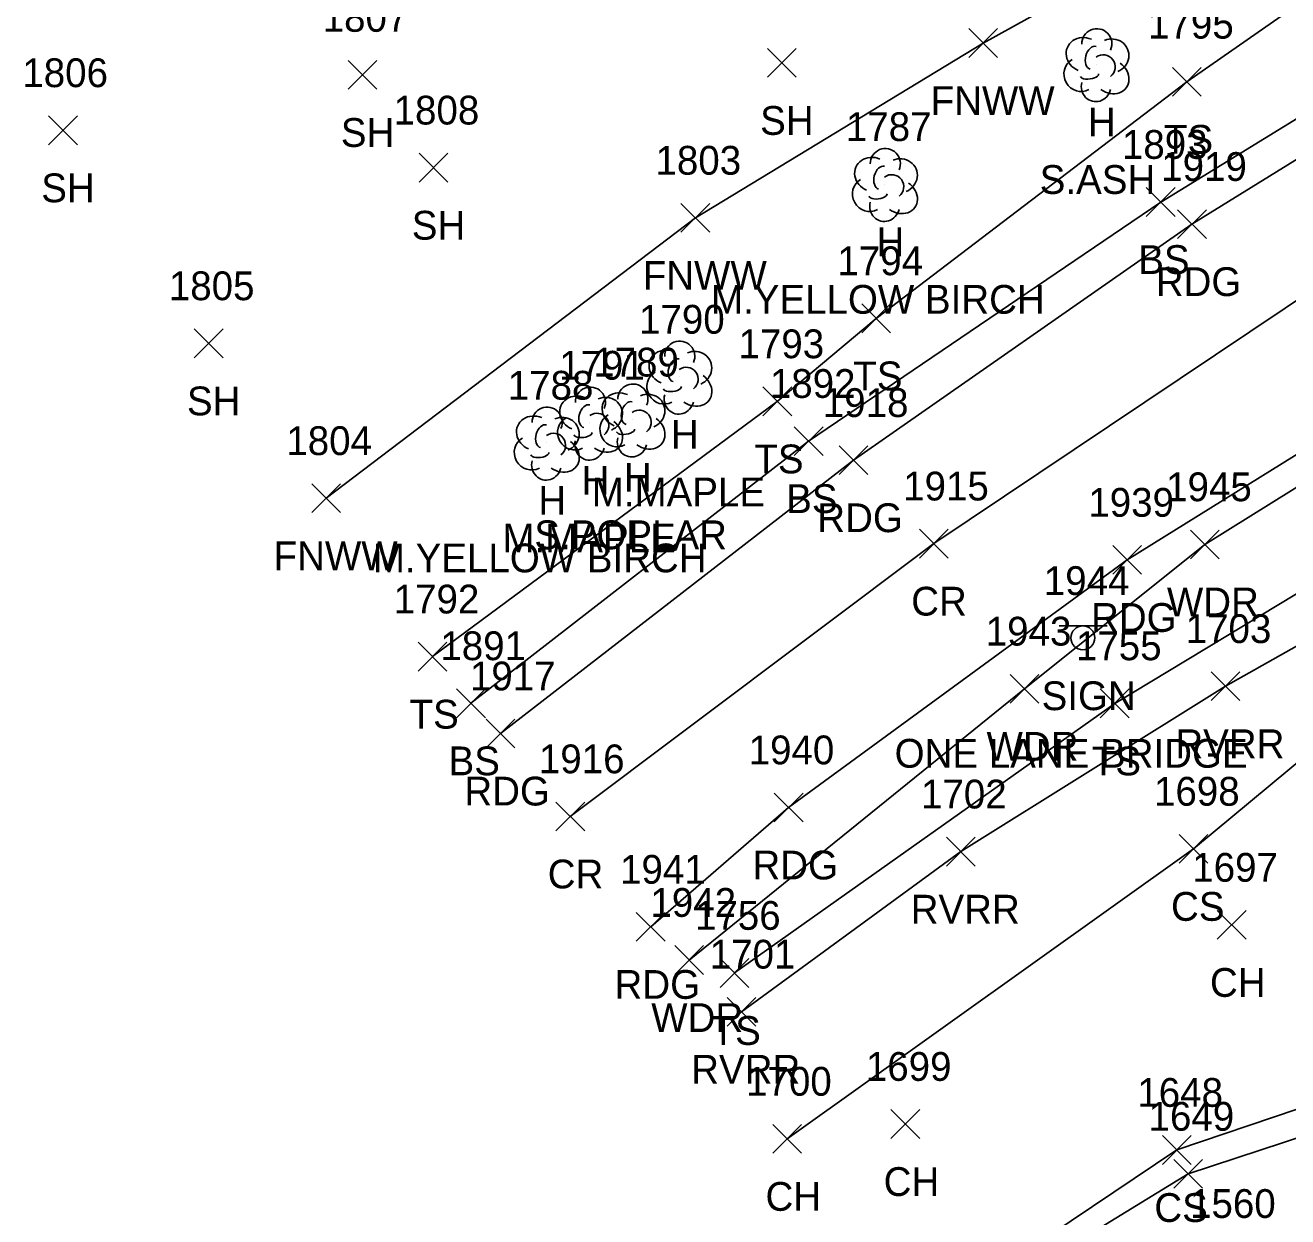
# Model space of a CAD drawing. Extents: x 1621633 to 1624015, y 417863 to 420979.
# Drawn here: x 1621633.1 to 1621720.8, y 417953.8 to 418036.6 of the extents above; entities that cross this region are included whole.
import ezdxf

# ---------------------------------------------------------------- set-up
doc = ezdxf.new("R2010")
doc.units = 0
for name, color, linetype in [('L_A', 7, 'Continuous'), ('L_C', 7, 'Continuous'), ('L_I', 7, 'Continuous'), ('L_TIC', 7, 'Continuous'), ('LAWA', 7, 'Continuous'), ('LAWE', 7, 'Continuous'), ('LELB', 7, 'Continuous'), ('LFNC', 7, 'Continuous'), ('LTD', 7, 'Continuous'), ('P_A', 7, 'Continuous'), ('P_I', 7, 'Continuous'), ('P_TIC', 7, 'Continuous'), ('PEU', 7, 'Continuous'), ('PRC', 7, 'Continuous'), ('S_A', 7, 'Continuous'), ('S_C', 7, 'Continuous'), ('S_I', 7, 'Continuous'), ('SSGN', 7, 'Continuous')]:
    doc.layers.add(name, color=color, linetype=linetype)

msp = doc.modelspace()

# ---------------------------------------------------------------- linework, layer by layer
at = {"layer": 'L_TIC'}
for points in [[(1621698.616, 418034.317), (1621700.616, 418036.317)], [(1621700.616, 418034.317), (1621698.616, 418036.317)], [(1621684.631, 418032.936), (1621686.631, 418034.936)], [(1621686.631, 418032.936), (1621684.631, 418034.936)], [(1621655.507, 418032.1), (1621657.507, 418034.1)], [(1621657.507, 418032.1), (1621655.507, 418034.1)], [(1621712.758, 418031.625), (1621714.758, 418033.625)], [(1621714.758, 418031.625), (1621712.758, 418033.625)], [(1621634.699, 418028.253), (1621636.699, 418030.253)], [(1621636.699, 418028.253), (1621634.699, 418030.253)], [(1621660.434, 418025.655), (1621662.434, 418027.655)], [(1621662.434, 418025.655), (1621660.434, 418027.655)], [(1621710.941, 418023.269), (1621712.941, 418025.269)], [(1621712.941, 418023.269), (1621710.941, 418025.269)], [(1621678.621, 418022.169), (1621680.621, 418024.169)], [(1621680.621, 418022.169), (1621678.621, 418024.169)], [(1621691.18, 418015.185), (1621693.18, 418017.185)], [(1621693.18, 418015.185), (1621691.18, 418017.185)], [(1621644.819, 418013.447), (1621646.819, 418015.447)], [(1621646.819, 418013.447), (1621644.819, 418015.447)], [(1621684.31, 418009.415), (1621686.31, 418011.415)], [(1621686.31, 418009.415), (1621684.31, 418011.415)], [(1621686.487, 418006.656), (1621688.487, 418008.656)], [(1621688.487, 418006.656), (1621686.487, 418008.656)], [(1621652.982, 418002.684), (1621654.982, 418004.684)], [(1621654.982, 418002.684), (1621652.982, 418004.684)], [(1621714.012, 417999.477), (1621716.012, 418001.477)], [(1621716.012, 417999.477), (1621714.012, 418001.477)], [(1621660.358, 417991.677), (1621662.358, 417993.677)], [(1621662.358, 417991.677), (1621660.358, 417993.677)], [(1621701.483, 417989.446), (1621703.483, 417991.446)], [(1621703.483, 417989.446), (1621701.483, 417991.446)], [(1621715.448, 417989.621), (1621717.448, 417991.621)], [(1621717.448, 417989.621), (1621715.448, 417991.621)], [(1621663.034, 417988.432), (1621665.034, 417990.432)], [(1621665.034, 417988.432), (1621663.034, 417990.432)], [(1621707.748, 417988.428), (1621709.748, 417990.428)], [(1621709.748, 417988.428), (1621707.748, 417990.428)], [(1621697.064, 417978.126), (1621699.064, 417980.126)], [(1621699.064, 417978.126), (1621697.064, 417980.126)], [(1621713.218, 417978.319), (1621715.218, 417980.319)], [(1621715.218, 417978.319), (1621713.218, 417980.319)], [(1621715.875, 417973.035), (1621717.875, 417975.035)], [(1621717.875, 417973.035), (1621715.875, 417975.035)], [(1621678.191, 417970.595), (1621680.191, 417972.595)], [(1621680.191, 417970.595), (1621678.191, 417972.595)], [(1621681.341, 417969.694), (1621683.341, 417971.694)], [(1621683.341, 417969.694), (1621681.341, 417971.694)], [(1621681.822, 417966.998), (1621683.822, 417968.998)], [(1621683.822, 417966.998), (1621681.822, 417968.998)], [(1621693.209, 417959.197), (1621695.209, 417961.197)], [(1621695.209, 417959.197), (1621693.209, 417961.197)], [(1621685.004, 417958.166), (1621687.004, 417960.166)], [(1621687.004, 417958.166), (1621685.004, 417960.166)], [(1621712.058, 417957.392), (1621714.058, 417959.392)], [(1621714.058, 417957.392), (1621712.058, 417959.392)], [(1621712.846, 417955.733), (1621714.846, 417957.733)], [(1621714.846, 417955.733), (1621712.846, 417957.733)]]:
    msp.add_lwpolyline(points, dxfattribs=at)
at = {"layer": 'LAWA'}
msp.add_lwpolyline([(1621679.191, 417971.595), (1621702.483, 417990.446), (1621715.012, 418000.477), (1621736.638, 418013.959), (1621752.876, 418023.199), (1621756.92, 418025.879), (1621771.105, 418032.081), (1621799.594, 418044.877), (1621821.796, 418051.595), (1621846.965, 418058.282), (1621864.113, 418063.689), (1621891.562, 418069.816), (1621913.254, 418074.106), (1621937.152, 418070.696)], dxfattribs=at)
at = {"layer": 'LAWE'}
for points in [[(1621694.469, 417944.857), (1621713.846, 417956.733), (1621742.172, 417966.049), (1621760.532, 417975.456), (1621777.237, 417983.398), (1621792.696, 417991.301), (1621817.095, 418001.163), (1621844.467, 418008.037), (1621871.363, 418013.308), (1621897.422, 418019.495), (1621922.912, 418028.804), (1621945.859, 418038.978), (1621969.359, 418051.535), (1621990.012, 418069.674), (1621996.064, 418084.217), (1621996.533, 418092.287)], [(1621682.822, 417967.998), (1621698.064, 417979.126), (1621716.448, 417990.621), (1621740.687, 418004.296), (1621760.276, 418012.676), (1621779.786, 418018.1), (1621807.782, 418023.044), (1621832.841, 418028.899), (1621852.452, 418034.783), (1621876.37, 418040.125), (1621904.646, 418043.594), (1621931.259, 418052.925), (1621950.617, 418064.927), (1621964.804, 418074.349), (1621971.864, 418081.724)]]:
    msp.add_lwpolyline(points, dxfattribs=at)
at = {"layer": 'LELB'}
for points in [[(1621664.034, 417989.432), (1621687.487, 418007.656), (1621711.941, 418024.269), (1621730.307, 418035.534), (1621752.55, 418048.381), (1621767.69, 418055.001), (1621798.303, 418066.249), (1621826.915, 418075.928), (1621858.253, 418085.298), (1621888.981, 418092.531), (1621914.256, 418098.407), (1621930.996, 418100.467)], [(1621694.018, 417945.604), (1621713.058, 417958.392), (1621741.418, 417968.002), (1621759.92, 417977.729), (1621776.332, 417984.988), (1621792.046, 417992.579), (1621816.284, 418002.68), (1621844.088, 418009.589), (1621869.849, 418015.692), (1621896.837, 418021.913), (1621921.805, 418030.632), (1621944.897, 418041.057), (1621968.773, 418053.066), (1621989.111, 418070.538), (1621994.262, 418084.512), (1621994.522, 418092.07)], [(1621714.218, 417979.319), (1621742.211, 418002.577), (1621762.579, 418009.214), (1621780.28, 418013.608), (1621808.258, 418019.376), (1621833.473, 418026.83), (1621853.516, 418030.646), (1621878.098, 418035.973), (1621904.446, 418042.094), (1621933.372, 418049.997), (1621951.553, 418063.416), (1621967.003, 418072.955), (1621972.682, 418081.713), (1621977.304, 418089.793)], [(1621661.358, 417992.677), (1621685.31, 418010.415), (1621692.18, 418016.185), (1621713.758, 418032.625), (1621737.079, 418048.878), (1621750.333, 418059.715), (1621751.345, 418064.166)], [(1621870.082, 418049.389), (1621847.864, 418048.319), (1621821.87, 418043.443), (1621810.848, 418041.046), (1621801.708, 418037.161), (1621779.745, 418029.631), (1621758.68, 418020.378), (1621745.692, 418010.927), (1621727.629, 418000.827), (1621708.748, 417989.428), (1621682.341, 417970.694)], [(1621714.218, 417979.319), (1621686.004, 417959.166)]]:
    msp.add_lwpolyline(points, dxfattribs=at)
at = {"layer": 'LFNC'}
msp.add_lwpolyline([(1621754.171, 418068.102), (1621747.634, 418062.695), (1621724.485, 418049.102), (1621699.616, 418035.317), (1621679.621, 418023.169), (1621653.982, 418003.684)], dxfattribs=at)
at = {"layer": 'LTD'}
for p, q in [((1621707.459, 418033.833), (1621707.459, 418033.833)), ((1621707.459, 418033.833), (1621707.459, 418033.833)), ((1621692.768, 418025.506), (1621692.768, 418025.506)), ((1621692.768, 418025.506), (1621692.768, 418025.506)), ((1621678.489, 418012.12), (1621678.489, 418012.12)), ((1621678.489, 418012.12), (1621678.489, 418012.12)), ((1621672.286, 418008.924), (1621672.286, 418008.924)), ((1621672.286, 418008.924), (1621672.286, 418008.924)), ((1621675.23, 418009.143), (1621675.23, 418009.143)), ((1621675.23, 418009.143), (1621675.23, 418009.143)), ((1621669.282, 418007.535), (1621669.282, 418007.535)), ((1621669.282, 418007.535), (1621669.282, 418007.535))]:
    msp.add_line(p, q, dxfattribs=at)
for centre in [(1621707.505, 418035.267), (1621692.815, 418026.94), (1621678.536, 418013.554), (1621675.277, 418010.577), (1621672.333, 418010.358), (1621669.329, 418008.968)]:
    msp.add_arc(centre, 1.047, 335.52715, 180.95627, dxfattribs=at)
for centre, major_axis, ratio, start_param, end_param in [((1621706.667, 418034.499), (1.21, -0.512), 0.895232, 1.570796, 4.712389), ((1621707.25, 418034.291), (-0.208, -0.792), 0.645439, 3.141593, 6.283185), ((1621708.5, 418034.416), (-1.141, -0.483), 0.949671, 1.570796, 4.712389), ((1621707.959, 418033.666), (-0.5, 0.667), 0.989748, 3.141593, 6.283185), ((1621706.376, 418033.124), (0.584, -1.042), 0.959034, 3.141593, 6.283185), ((1621708.459, 418033), (-1.09, 0.792), 0.841452, 1.570796, 4.712389), ((1621707.459, 418032.333), (0.265, 1.061), 0.942809, 1.570796, 4.712389), ((1621707.001, 418033.083), (-0.625, -0.083), 0.423636, 0, 3.141593), ((1621691.977, 418026.173), (1.21, -0.512), 0.895232, 1.570796, 4.712389), ((1621693.81, 418026.09), (-1.141, -0.483), 0.949671, 1.570796, 4.712389), ((1621692.56, 418025.964), (-0.208, -0.792), 0.645439, 3.141593, 6.283185), ((1621691.685, 418024.798), (0.584, -1.042), 0.959034, 3.141593, 6.283185), ((1621693.268, 418025.34), (-0.5, 0.667), 0.989748, 3.141593, 6.283185), ((1621693.769, 418024.673), (-1.09, 0.792), 0.841452, 1.570796, 4.712389), ((1621692.31, 418024.756), (-0.625, -0.083), 0.423636, 0, 3.141593), ((1621692.769, 418024.006), (0.265, 1.061), 0.942809, 1.570796, 4.712389), ((1621677.697, 418012.787), (1.21, -0.512), 0.895232, 1.570796, 4.712389), ((1621679.531, 418012.704), (-1.141, -0.483), 0.949671, 1.570796, 4.712389), ((1621678.281, 418012.579), (-0.208, -0.792), 0.645439, 3.141593, 6.283185), ((1621677.406, 418011.412), (0.584, -1.042), 0.959034, 3.141593, 6.283185), ((1621678.989, 418011.954), (-0.5, 0.667), 0.989748, 3.141593, 6.283185), ((1621678.031, 418011.37), (-0.625, -0.083), 0.423636, 0, 3.141593), ((1621679.489, 418011.287), (-1.09, 0.792), 0.841452, 1.570796, 4.712389), ((1621671.494, 418009.591), (1.21, -0.512), 0.895232, 1.570796, 4.712389), ((1621673.328, 418009.508), (-1.141, -0.483), 0.949671, 1.570796, 4.712389), ((1621674.438, 418009.809), (1.21, -0.512), 0.895232, 1.570796, 4.712389), ((1621676.272, 418009.726), (-1.141, -0.483), 0.949671, 1.570796, 4.712389), ((1621678.489, 418010.62), (0.265, 1.061), 0.942809, 1.570796, 4.712389), ((1621672.078, 418009.382), (-0.208, -0.792), 0.645439, 3.141593, 6.283185), ((1621672.786, 418008.758), (-0.5, 0.667), 0.989748, 3.141593, 6.283185), ((1621675.022, 418009.601), (-0.208, -0.792), 0.645439, 3.141593, 6.283185), ((1621675.73, 418008.976), (-0.5, 0.667), 0.989748, 3.141593, 6.283185), ((1621668.49, 418008.201), (1.21, -0.512), 0.895232, 1.570796, 4.712389), ((1621669.073, 418007.993), (-0.208, -0.792), 0.645439, 3.141593, 6.283185), ((1621670.323, 418008.118), (-1.141, -0.483), 0.949671, 1.570796, 4.712389), ((1621671.203, 418008.216), (0.584, -1.042), 0.959034, 3.141593, 6.283185), ((1621673.286, 418008.091), (-1.09, 0.792), 0.841452, 1.570796, 4.712389), ((1621674.147, 418008.434), (0.584, -1.042), 0.959034, 3.141593, 6.283185), ((1621676.23, 418008.31), (-1.09, 0.792), 0.841452, 1.570796, 4.712389), ((1621669.782, 418007.368), (-0.5, 0.667), 0.989748, 3.141593, 6.283185), ((1621671.828, 418008.174), (-0.625, -0.083), 0.423636, 0, 3.141593), ((1621674.772, 418008.393), (-0.625, -0.083), 0.423636, 0, 3.141593), ((1621668.199, 418006.826), (0.584, -1.042), 0.959034, 3.141593, 6.283185), ((1621670.282, 418006.701), (-1.09, 0.792), 0.841452, 1.570796, 4.712389), ((1621672.286, 418007.424), (0.265, 1.061), 0.942809, 1.570796, 4.712389), ((1621675.23, 418007.643), (0.265, 1.061), 0.942809, 1.570796, 4.712389), ((1621669.282, 418006.035), (0.265, 1.061), 0.942809, 1.570796, 4.712389), ((1621668.824, 418006.784), (-0.625, -0.083), 0.423636, 0, 3.141593)]:
    msp.add_ellipse(centre, major_axis=major_axis, ratio=ratio, start_param=start_param, end_param=end_param, dxfattribs=at)
at = {"layer": 'P_TIC'}
for points in [[(1621713.112, 418021.734), (1621715.112, 418023.734)], [(1621715.112, 418021.734), (1621713.112, 418023.734)], [(1621689.601, 418005.329), (1621691.601, 418007.329)], [(1621691.601, 418005.329), (1621689.601, 418007.329)], [(1621695.18, 417999.53), (1621697.18, 418001.53)], [(1621697.18, 417999.53), (1621695.18, 418001.53)], [(1621708.615, 417998.398), (1621710.615, 418000.398)], [(1621710.615, 417998.398), (1621708.615, 418000.398)], [(1621665.087, 417986.333), (1621667.087, 417988.333)], [(1621667.087, 417986.333), (1621665.087, 417988.333)], [(1621669.933, 417980.571), (1621671.933, 417982.571)], [(1621671.933, 417980.571), (1621669.933, 417982.571)], [(1621685.1, 417981.194), (1621687.1, 417983.194)], [(1621687.1, 417981.194), (1621685.1, 417983.194)], [(1621675.517, 417972.897), (1621677.517, 417974.897)], [(1621677.517, 417972.897), (1621675.517, 417974.897)]]:
    msp.add_lwpolyline(points, dxfattribs=at)
at = {"layer": 'PEU'}
for points in [[(1621666.087, 417987.333), (1621690.601, 418006.329), (1621714.112, 418022.734), (1621739.503, 418038.461), (1621766, 418052.456), (1621797.985, 418064.445), (1621829.098, 418075.197), (1621862.236, 418084.699), (1621894.034, 418092.423)], [(1621912.204, 418078.592), (1621880.997, 418070.288), (1621848.822, 418062.508), (1621818.735, 418053.659), (1621789.443, 418043.868), (1621760.318, 418029.904), (1621735.432, 418015.464), (1621709.615, 417999.398), (1621686.1, 417982.194), (1621676.517, 417973.897)]]:
    msp.add_lwpolyline(points, dxfattribs=at)
at = {"layer": 'PRC'}
msp.add_lwpolyline([(1621971.067, 418099.341), (1621938.438, 418093.726), (1621906.629, 418086.952), (1621874.869, 418079.941), (1621842.519, 418071.194), (1621811.531, 418061.42), (1621780.514, 418050.109), (1621750.947, 418035.3), (1621723.041, 418018.53), (1621696.18, 418000.53), (1621670.933, 417981.571)], dxfattribs=at)
at = {"layer": 'SSGN'}
for p, q in [((1621704.888, 417994.812), (1621708.221, 417994.812)), ((1621706.534, 417993.979), (1621706.534, 417993.979))]:
    msp.add_line(p, q, dxfattribs=at)
msp.add_circle((1621706.534, 417993.979), 0.833, dxfattribs=at)

# ---------------------------------------------------------------- texts
at = {"layer": 'L_A'}
for s, p in [('FNWW', (1621695.963, 418030.317)), ('SH', (1621684.119, 418028.936)), ('H', (1621706.892, 418028.833)), ('SH', (1621654.995, 418028.1)), ('TS', (1621712.167, 418027.625)), ('SH', (1621634.187, 418024.253)), ('SH', (1621659.922, 418021.655)), ('H', (1621692.201, 418020.506)), ('BS', (1621710.382, 418019.269)), ('FNWW', (1621675.968, 418018.169)), ('TS', (1621690.589, 418011.185)), ('SH', (1621644.308, 418009.447)), ('H', (1621677.922, 418007.12)), ('TS', (1621683.719, 418005.415)), ('H', (1621671.719, 418003.924)), ('H', (1621674.663, 418004.143)), ('H', (1621668.715, 418002.535)), ('BS', (1621685.928, 418002.656)), ('FNWW', (1621650.328, 417998.684)), ('WDR', (1621712.374, 417995.477)), ('TS', (1621659.767, 417987.677)), ('WDR', (1621699.845, 417985.446)), ('RVRR', (1621712.96, 417985.621)), ('BS', (1621662.475, 417984.432)), ('TS', (1621707.158, 417984.428)), ('CS', (1621712.659, 417974.319)), ('RVRR', (1621694.576, 417974.126)), ('CH', (1621715.363, 417969.035)), ('WDR', (1621676.554, 417966.595)), ('TS', (1621680.75, 417965.694)), ('RVRR', (1621679.333, 417962.998)), ('CH', (1621692.697, 417955.197)), ('CH', (1621684.492, 417954.166)), ('CS', (1621711.499, 417953.392))]:
    msp.add_text(s, height=2, dxfattribs=at).set_placement(p)
at = {"layer": 'L_C'}
for s, p in [('S.ASH', (1621703.537, 418024.833)), ('M.YELLOW BIRCH', (1621680.705, 418016.506)), ('M.MAPLE', (1621672.426, 418003.12)), ('M.MAPLE', (1621666.223, 417999.924)), ('S.POPLAR', (1621668.435, 418000.143)), ('M.YELLOW BIRCH', (1621657.219, 417998.535))]:
    msp.add_text(s, height=2, dxfattribs=at).set_placement(p)
at = {"layer": 'L_I'}
for s, p in [('1807', (1621653.735, 418036.1)), ('1795', (1621711.065, 418035.625)), ('1806', (1621632.872, 418032.253)), ('1808', (1621658.662, 418029.655)), ('1787', (1621690.075, 418028.506)), ('1893', (1621709.248, 418027.269)), ('1803', (1621676.85, 418026.169)), ('1794', (1621689.487, 418019.185)), ('1805', (1621643.048, 418017.447)), ('1790', (1621675.71, 418015.12)), ('1793', (1621682.617, 418013.415)), ('1789', (1621672.529, 418012.143)), ('1791', (1621670.16, 418011.924)), ('1788', (1621666.589, 418010.535)), ('1892', (1621684.794, 418010.656)), ('1804', (1621651.21, 418006.684)), ('1945', (1621712.319, 418003.477)), ('1792', (1621658.665, 417995.677)), ('1703', (1621713.677, 417993.621)), ('1943', (1621699.79, 417993.446)), ('1891', (1621661.908, 417992.432)), ('1755', (1621706.055, 417992.428)), ('1698', (1621711.478, 417982.319)), ('1702', (1621695.293, 417982.126)), ('1697', (1621714.135, 417977.035)), ('1942', (1621676.499, 417974.595)), ('1756', (1621679.593, 417973.694)), ('1701', (1621680.617, 417970.998)), ('1699', (1621691.461, 417963.197)), ('1700', (1621683.145, 417962.166)), ('1648', (1621710.318, 417961.392)), ('1649', (1621711.098, 417959.733)), ('1560', (1621713.981, 417953.671))]:
    msp.add_text(s, height=2, dxfattribs=at).set_placement(p)
at = {"layer": 'P_A'}
for s, p in [('RDG', (1621711.6, 418017.734)), ('RDG', (1621688.089, 418001.329)), ('CR', (1621694.613, 417995.53)), ('RDG', (1621707.104, 417994.398)), ('RDG', (1621663.575, 417982.333)), ('RDG', (1621683.588, 417977.194)), ('CR', (1621669.366, 417976.571)), ('RDG', (1621674.006, 417968.897))]:
    msp.add_text(s, height=2, dxfattribs=at).set_placement(p)
at = {"layer": 'P_I'}
for s, p in [('1919', (1621711.978, 418025.734)), ('1918', (1621688.475, 418009.329)), ('1915', (1621694.054, 418003.53)), ('1939', (1621706.915, 418002.398)), ('1917', (1621663.961, 417990.333)), ('1940', (1621683.321, 417985.194)), ('1916', (1621668.752, 417984.571)), ('1941', (1621674.391, 417976.897))]:
    msp.add_text(s, height=2, dxfattribs=at).set_placement(p)
at = {"layer": 'S_A'}
msp.add_text('SIGN', height=2, dxfattribs=at).set_placement((1621703.672, 417988.959))
at = {"layer": 'S_C'}
msp.add_text('ONE LANE BRIDGE', height=2, dxfattribs=at).set_placement((1621693.46, 417984.959))
at = {"layer": 'S_I'}
msp.add_text('1944', height=2, dxfattribs=at).set_placement((1621703.822, 417996.959))

doc.saveas('drawing.dxf')
